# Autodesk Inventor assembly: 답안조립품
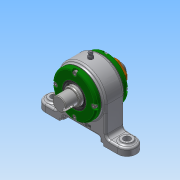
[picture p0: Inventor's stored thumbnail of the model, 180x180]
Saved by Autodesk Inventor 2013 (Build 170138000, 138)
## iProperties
Created: 2019-05
Part Number: 답안조립품
Document SubType Name: Assembly
Designer: Administrator
Author: Administrator
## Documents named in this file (13)
- C:\Users\Administrator\Desktop\490504V1006\답안조립품.iam
- C:\Users\Administrator\Desktop\490504V1006\본체.ipt
- C:\Users\Administrator\Desktop\490504V1006\개스킷.ipt
- C:\Users\Administrator\Desktop\490504V1006\그리스니플 M6.ipt
- 그리스니플  M6.ipt
- C:\Users\Administrator\Desktop\490504V1006\그리스니플개스킷.ipt
- C:\Users\Administrator\Desktop\490504V1006\베어링너트.ipt
- C:\Users\Administrator\Desktop\490504V1006\볼트 M4.ipt
- C:\Users\Administrator\Desktop\490504V1006\앵귤러 볼 베어링 7205.ipt
- C:\Users\Administrator\Desktop\490504V1006\오일 실 28 40 5 B.ipt
- C:\Users\Administrator\Desktop\490504V1006\축.ipt
- C:\Users\Administrator\Desktop\490504V1006\칼라.ipt
- C:\Users\Administrator\Desktop\490504V1006\커버.ipt
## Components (4 placed, 3 different names)
1. 개스킷:1
2. 그리스니플  M6:1
3. 그리스니플개스킷:1
4. 개스킷:2
